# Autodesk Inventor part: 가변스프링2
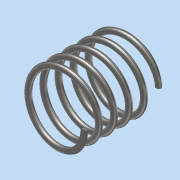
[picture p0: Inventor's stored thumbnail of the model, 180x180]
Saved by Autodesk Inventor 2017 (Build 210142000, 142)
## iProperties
Part Number: 가변스프링2
Material: 강철, 연강
Document SubType Name: Modeling
Designer: MRC
Density: 7.85 g/cm^3
Appearance: 반연마
Mass: 8.39036 g
Surface Area: 21.6653 cm^2
Volume: 1.06884 cm^3
Author: MRC
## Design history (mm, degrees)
sketch "스케치1"
  geometry: L1 (0, 0)-(11, 0); L2 (11, 0)-(11, 26.358); L3 (11, 26.358)-(0, 26.358); L4 (0, 26.358)-(0, 0); C1 r 1 at (11, 0)
  constraints: 8 end point, 2 parallel, 1 centre point, 1 coincident, 1 horizontal, 1 perpendicular
  dimensions: "d0" = 22 diameter of L2 L4; "d1" = 2 diameter of C1; "d2" = 26.35829 distance between parallel lines of L1 L3 (derived)
feature "코일1" sketch "스케치1" pitch "d3" = 10; turns "d5" = 5; dims "d4" = 26.35829 (= d2), "d6" = 0, angle "d7" = 90 deg, angle "d8" = 90 deg, "d9" = 0, "d10" = 0
sketch "스케치2"
  geometry: L1 (-25.076, 26.358)-(25.076, 26.358); L2 (25.076, 26.358)-(25.076, 0); L3 (25.076, 0)-(-25.076, 0); L4 (-25.076, 0)-(-25.076, 26.358); L5 (0, 26.358)-(0, 0) reference; 2 further points
  constraints: 8 end point, 2 midpoint, 2 parallel, 1 coincident, 1 horizontal, 1 perpendicular
  dimensions: "d11" = 50.15108 distance of L1.start L1.end
extrude "돌출1" sketch "스케치2" stored distance "d12" = 0; taper "d13" = 0 deg
node "솔리드1"
